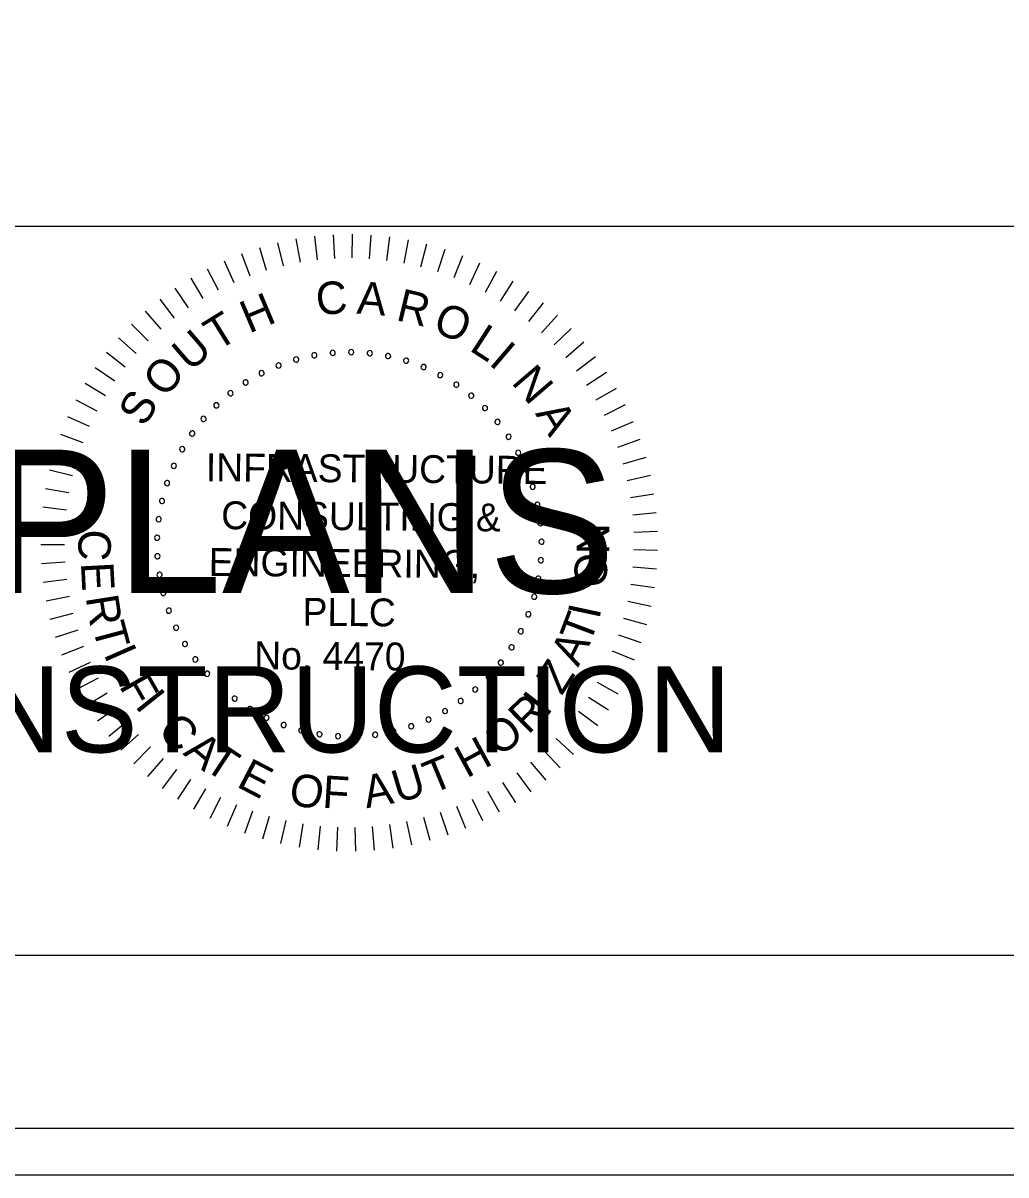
# Model space of a CAD drawing. Extents: x 967 to 1326, y 964 to 3144.
# Drawn here: x 1189.3 to 1212.88, y 963.72 to 991.36 of the extents above; entities that cross this region are included whole.
import ezdxf

# ---------------------------------------------------------------- set-up
doc = ezdxf.new("R2010")
doc.units = 0
for name, color, linetype in [('RD_XS_EwShp', 7, 'Continuous'), ('RD_XS_ExPaveRet', 7, 'Continuous'), ('RD_XS_TX_Elev_EX', 7, 'Continuous'), ('RD_XS_TX_Elev_PR', 7, 'Continuous'), ('RD_XS_TX_Station', 7, 'Continuous')]:
    doc.layers.add(name, color=color, linetype=linetype)

msp = doc.modelspace()

# ---------------------------------------------------------------- linework, layer by layer
at = {"layer": 'RD_XS_ExPaveRet'}
for points in [[(967.409, 963.72), (1326.285, 963.72), (1326.285, 1183.72), (967.409, 1183.72)], [(988.525, 964.84), (1326.285, 964.84), (1326.285, 1182.6), (988.525, 1182.6)]]:
    msp.add_lwpolyline(points, close=True, dxfattribs=at)
at = {"layer": 'RD_XS_TX_Elev_EX'}
for p, q in [((996.114, 986.486), (1323.886, 986.486)), ((1323.886, 968.983), (996.114, 968.983))]:
    msp.add_line(p, q, dxfattribs=at)
at = {"layer": 'RD_XS_TX_Elev_PR'}
for p, q in [((1196.292, 986.245), (1196.357, 985.68)), ((1196.742, 986.282), (1196.772, 985.714)), ((1197.194, 986.292), (1197.189, 985.723)), ((1197.645, 986.274), (1197.606, 985.706)), ((1198.094, 986.228), (1198.02, 985.664)), ((1194.968, 985.971), (1195.134, 985.427)), ((1195.403, 986.09), (1195.536, 985.536)), ((1195.846, 986.181), (1195.945, 985.62)), ((1198.54, 986.156), (1198.432, 985.596)), ((1198.98, 986.056), (1198.838, 985.504)), ((1199.414, 985.929), (1199.238, 985.387)), ((1194.122, 985.656), (1194.353, 985.136)), ((1194.54, 985.827), (1194.739, 985.293)), ((1199.839, 985.777), (1199.63, 985.246)), ((1193.715, 985.461), (1193.978, 984.956)), ((1200.253, 985.598), (1200.013, 985.082)), ((1200.656, 985.395), (1200.385, 984.894)), ((1193.321, 985.241), (1193.614, 984.752)), ((1201.047, 985.167), (1200.745, 984.684)), ((1192.94, 984.997), (1193.263, 984.528)), ((1201.422, 984.917), (1201.092, 984.453)), ((1192.576, 984.731), (1192.926, 984.282)), ((1201.781, 984.643), (1201.424, 984.2)), ((1192.228, 984.443), (1192.605, 984.016)), ((1202.124, 984.349), (1201.739, 983.928)), ((1191.899, 984.134), (1192.301, 983.731)), ((1202.447, 984.034), (1202.038, 983.638)), ((1191.589, 983.805), (1192.015, 983.428)), ((1202.751, 983.7), (1202.318, 983.329)), ((1191.299, 983.459), (1191.748, 983.108)), ((1203.034, 983.348), (1202.579, 983.004)), ((1191.032, 983.095), (1191.501, 982.772)), ((1203.294, 982.979), (1202.82, 982.664)), ((1190.787, 982.716), (1191.274, 982.422)), ((1203.532, 982.595), (1203.04, 982.31)), ((1190.565, 982.323), (1191.07, 982.059)), ((1203.746, 982.198), (1203.237, 981.943)), ((1190.368, 981.916), (1190.888, 981.684)), ((1203.936, 981.788), (1203.412, 981.564)), ((1190.196, 981.499), (1190.729, 981.299)), ((1204.1, 981.367), (1203.563, 981.176)), ((1190.05, 981.072), (1190.594, 980.905)), ((1204.238, 980.937), (1203.691, 980.779)), ((1189.93, 980.636), (1190.484, 980.503)), ((1204.349, 980.5), (1203.794, 980.375)), ((1189.837, 980.195), (1190.398, 980.095)), ((1204.434, 980.056), (1203.872, 979.966)), ((1189.771, 979.748), (1190.337, 979.683)), ((1204.491, 979.608), (1203.925, 979.552)), ((1189.732, 979.298), (1190.301, 979.267)), ((1204.522, 979.158), (1203.953, 979.137)), ((1189.721, 978.847), (1190.29, 978.851)), ((1204.524, 978.706), (1203.955, 978.72)), ((1189.737, 978.396), (1190.306, 978.434)), ((1204.499, 978.256), (1203.932, 978.304)), ((1189.781, 977.946), (1190.346, 978.019)), ((1204.447, 977.807), (1203.884, 977.89)), ((1189.852, 977.5), (1190.412, 977.608)), ((1204.367, 977.363), (1203.81, 977.479)), ((1189.951, 977.06), (1190.502, 977.201)), ((1204.261, 976.924), (1203.712, 977.074)), ((1190.076, 976.626), (1190.617, 976.8)), ((1204.128, 976.492), (1203.589, 976.676)), ((1190.227, 976.2), (1190.757, 976.408)), ((1203.969, 976.07), (1203.442, 976.286)), ((1190.403, 975.785), (1190.92, 976.024)), ((1203.784, 975.658), (1203.271, 975.906)), ((1190.605, 975.381), (1191.106, 975.651)), ((1203.574, 975.258), (1203.078, 975.537)), ((1190.831, 974.99), (1191.315, 975.291)), ((1203.341, 974.871), (1202.862, 975.18)), ((1191.081, 974.614), (1191.545, 974.943)), ((1191.353, 974.253), (1191.796, 974.61)), ((1203.085, 974.5), (1202.626, 974.837)), ((1202.806, 974.145), (1202.368, 974.509)), ((1191.646, 973.91), (1192.067, 974.293)), ((1202.506, 973.807), (1202.092, 974.197)), ((1191.96, 973.585), (1192.356, 973.994)), ((1202.186, 973.488), (1201.796, 973.903)), ((1192.293, 973.28), (1192.664, 973.712)), ((1201.847, 973.19), (1201.484, 973.628)), ((1192.644, 972.996), (1192.988, 973.45)), ((1193.011, 972.734), (1193.327, 973.208)), ((1201.491, 972.912), (1201.155, 973.372)), ((1193.394, 972.495), (1193.68, 972.987)), ((1200.731, 972.425), (1200.453, 972.922)), ((1201.119, 972.657), (1200.811, 973.136)), ((1193.791, 972.279), (1194.047, 972.788)), ((1200.331, 972.217), (1200.083, 972.73)), ((1194.2, 972.088), (1194.424, 972.612)), ((1194.62, 971.923), (1194.812, 972.459)), ((1199.495, 971.877), (1199.312, 972.416)), ((1199.918, 972.034), (1199.702, 972.561)), ((1195.05, 971.783), (1195.208, 972.33)), ((1195.487, 971.67), (1195.612, 972.225)), ((1195.93, 971.584), (1196.021, 972.146)), ((1196.377, 971.524), (1196.434, 972.091)), ((1198.179, 971.562), (1198.097, 972.126)), ((1198.624, 971.64), (1198.508, 972.198)), ((1199.063, 971.745), (1198.913, 972.295)), ((1196.828, 971.493), (1196.85, 972.062)), ((1197.279, 971.488), (1197.267, 972.058)), ((1197.73, 971.512), (1197.683, 972.079))]:
    msp.add_line(p, q, dxfattribs=at)
for centre, start, end in [((1196.285, 983.388), 10.6038, 190.6038), ((1196.727, 983.447), 5.0653, 185.0653), ((1196.727, 983.447), 185.0653, 5.0653), ((1197.172, 983.464), 359.5268, 179.5268), ((1197.172, 983.464), 179.5268, 359.5268), ((1197.617, 983.438), 173.9884, 353.9884), ((1197.617, 983.438), 353.9884, 173.9884), ((1198.057, 983.369), 348.4499, 168.4499), ((1195.429, 983.142), 21.6807, 201.6807), ((1195.429, 983.142), 201.6807, 21.6807), ((1195.851, 983.285), 16.1422, 196.1422), ((1195.851, 983.285), 196.1422, 16.1422), ((1196.285, 983.388), 190.6038, 10.6038), ((1198.057, 983.369), 168.4499, 348.4499), ((1198.489, 983.258), 162.9114, 342.9114), ((1198.489, 983.258), 342.9114, 162.9114), ((1198.908, 983.106), 337.373, 157.373), ((1195.023, 982.958), 27.2191, 207.2191), ((1195.023, 982.958), 207.2191, 27.2191), ((1198.908, 983.106), 157.373, 337.373), ((1199.31, 982.914), 151.8345, 331.8345), ((1199.31, 982.914), 331.8345, 151.8345), ((1194.637, 982.736), 32.7576, 212.7576), ((1194.637, 982.736), 212.7576, 32.7576), ((1199.692, 982.684), 146.2961, 326.2961), ((1199.692, 982.684), 326.2961, 146.2961), ((1194.274, 982.478), 38.2961, 218.2961), ((1194.274, 982.478), 218.2961, 38.2961), ((1200.05, 982.419), 140.7576, 320.7576), ((1200.05, 982.419), 320.7576, 140.7576), ((1193.937, 982.186), 43.8345, 223.8345), ((1193.937, 982.186), 223.8345, 43.8345), ((1200.38, 982.12), 135.2191, 315.2191), ((1200.38, 982.12), 315.2191, 135.2191), ((1193.63, 981.862), 49.373, 229.373), ((1193.63, 981.862), 229.373, 49.373), ((1200.68, 981.79), 129.6807, 309.6807), ((1200.68, 981.79), 309.6807, 129.6807), ((1193.356, 981.511), 54.9114, 234.9114), ((1193.356, 981.511), 234.9114, 54.9114), ((1200.947, 981.433), 304.1422, 124.1422), ((1200.947, 981.433), 124.1422, 304.1422), ((1193.117, 981.135), 60.4499, 240.4499), ((1193.117, 981.135), 240.4499, 60.4499), ((1201.179, 981.052), 118.6038, 298.6038), ((1201.179, 981.052), 298.6038, 118.6038), ((1192.915, 980.737), 65.9884, 245.9884), ((1192.915, 980.737), 245.9884, 65.9884), ((1201.372, 980.651), 113.0653, 293.0653), ((1201.372, 980.651), 293.0653, 113.0653), ((1192.753, 980.322), 71.5268, 251.5268), ((1192.753, 980.322), 251.5268, 71.5268), ((1201.526, 980.233), 107.5268, 287.5268), ((1201.526, 980.233), 287.5268, 107.5268), ((1192.632, 979.894), 77.0653, 257.0653), ((1192.632, 979.894), 257.0653, 77.0653), ((1201.638, 979.801), 101.9884, 281.9884), ((1201.638, 979.801), 281.9884, 101.9884), ((1192.552, 979.455), 82.6038, 262.6038), ((1192.552, 979.455), 262.6038, 82.6038), ((1201.709, 979.361), 96.4499, 276.4499), ((1201.709, 979.361), 276.4499, 96.4499), ((1192.515, 979.011), 88.1422, 268.1422), ((1192.515, 979.011), 268.1422, 88.1422), ((1201.737, 978.917), 90.9114, 270.9114), ((1201.737, 978.917), 270.9114, 90.9114), ((1192.522, 978.565), 93.6807, 273.6807), ((1192.522, 978.565), 273.6807, 93.6807), ((1201.721, 978.471), 85.373, 265.373), ((1201.721, 978.471), 265.373, 85.373), ((1192.571, 978.122), 99.2191, 279.2191), ((1192.571, 978.122), 279.2191, 99.2191), ((1201.663, 978.029), 79.8345, 259.8345), ((1201.663, 978.029), 259.8345, 79.8345), ((1192.662, 977.686), 104.7576, 284.7576), ((1192.662, 977.686), 284.7576, 104.7576), ((1201.563, 977.595), 74.2961, 254.2961), ((1201.563, 977.595), 254.2961, 74.2961), ((1192.796, 977.261), 110.2961, 290.2961), ((1192.796, 977.261), 290.2961, 110.2961), ((1201.42, 977.173), 68.7576, 248.7576), ((1201.42, 977.173), 248.7576, 68.7576), ((1192.97, 976.851), 115.8345, 295.8345), ((1192.97, 976.851), 295.8345, 115.8345), ((1201.238, 976.766), 63.2191, 243.2191), ((1201.238, 976.766), 243.2191, 63.2191), ((1193.182, 976.459), 301.373, 121.373), ((1193.182, 976.459), 121.373, 301.373), ((1201.018, 976.379), 57.6807, 237.6807), ((1201.018, 976.379), 237.6807, 57.6807), ((1193.432, 976.09), 126.9114, 306.9114), ((1193.432, 976.09), 306.9114, 126.9114), ((1200.761, 976.014), 52.1422, 232.1422), ((1200.761, 976.014), 232.1422, 52.1422), ((1193.715, 975.746), 132.4499, 312.4499), ((1193.715, 975.746), 312.4499, 132.4499), ((1200.47, 975.677), 46.6038, 226.6038), ((1200.47, 975.677), 226.6038, 46.6038), ((1194.031, 975.431), 137.9884, 317.9884), ((1194.031, 975.431), 317.9884, 137.9884), ((1200.148, 975.369), 41.0653, 221.0653), ((1200.148, 975.369), 221.0653, 41.0653), ((1194.376, 975.149), 143.5268, 323.5268), ((1194.376, 975.149), 323.5268, 143.5268), ((1199.798, 975.093), 35.5268, 215.5268), ((1194.746, 974.901), 149.0653, 329.0653), ((1194.746, 974.901), 329.0653, 149.0653), ((1199.422, 974.853), 29.9884, 209.9884), ((1199.422, 974.853), 209.9884, 29.9884), ((1199.798, 975.093), 215.5268, 35.5268), ((1195.139, 974.69), 154.6038, 334.6038), ((1195.139, 974.69), 334.6038, 154.6038), ((1195.55, 974.517), 340.1422, 160.1422), ((1199.026, 974.65), 24.4499, 204.4499), ((1199.026, 974.65), 204.4499, 24.4499), ((1195.55, 974.517), 160.1422, 340.1422), ((1195.975, 974.386), 165.6807, 345.6807), ((1195.975, 974.386), 345.6807, 165.6807), ((1196.412, 974.295), 171.2191, 351.2191), ((1196.412, 974.295), 351.2191, 171.2191), ((1196.855, 974.248), 356.7576, 176.7576), ((1197.301, 974.243), 2.2961, 182.2961), ((1197.745, 974.282), 7.8345, 187.8345), ((1198.183, 974.363), 13.373, 193.373), ((1198.183, 974.363), 193.373, 13.373), ((1198.611, 974.486), 18.9114, 198.9114), ((1198.611, 974.486), 198.9114, 18.9114), ((1196.855, 974.248), 176.7576, 356.7576), ((1197.301, 974.243), 182.2961, 2.2961), ((1197.745, 974.282), 187.8345, 7.8345)]:
    msp.add_arc(centre, 0.0627, start, end, dxfattribs=at)
at = {"layer": 'RD_XS_TX_Station'}
msp.add_lwpolyline([(967.409, 963.72), (1326.285, 963.72), (1326.285, 1183.72), (967.409, 1183.72)], close=True, dxfattribs=at)

# ---------------------------------------------------------------- texts
at = {"layer": 'RD_XS_EwShp'}
for s, height, p in [('FINAL PLANS', 3.4375, (1174.145, 977.685)), ('NOT FOR CONSTRUCTION', 2.0625, (1170.901, 973.86))]:
    msp.add_text(s, height=height, dxfattribs=at).set_placement(p)
at = {"layer": 'RD_XS_TX_Elev_PR'}
for s, height, rotation, p in [('C', 0.78, 4.7281, (1196.355, 984.346)), ('A', 0.78, 355.6981, (1197.29, 984.39)), ('H', 0.78, 22.7882, (1194.72, 983.904)), ('R', 0.78, 346.6681, (1198.222, 984.238)), ('O', 0.78, 337.638, (1199.096, 983.972)), ('T', 0.78, 31.8182, (1193.961, 983.478)), ('U', 0.78, 40.8482, (1193.306, 982.976)), ('L', 0.78, 327.108, (1199.981, 983.52)), ('I', 0.78, 319.578, (1200.451, 983.182)), ('O', 0.78, 49.8782, (1192.707, 982.341)), ('N', 0.78, 310.548, (1200.994, 982.728)), ('S', 0.78, 58.9083, (1192.211, 981.642)), ('A', 0.78, 301.5179, (1201.576, 981.991)), ('INFRASTRUCTURE', 0.66873, 359.5268, (1193.682, 980.367)), ('CONSULTING &', 0.66873, 359.5268, (1194.051, 979.217)), ('N', 0.78, 89.2085, (1203.359, 978.604)), ('C', 0.78, 267.025, (1190.646, 979.227)), ('ENGINEERING,', 0.66873, 359.5268, (1193.751, 978.095)), ('O', 0.78, 83.2085, (1203.26, 977.786)), ('E', 0.78, 273.025, (1190.685, 978.408)), ('R', 0.78, 279.025, (1190.799, 977.583)), ('PLLC', 0.6687, 359.5268, (1196.002, 976.9)), ('I', 0.78, 77.9093, (1203.121, 977.032)), ('T', 0.78, 69.3954, (1202.891, 976.428)), ('T', 0.78, 285.025, (1190.955, 976.878)), ('No. 4470', 0.6687, 359.5268, (1194.843, 975.855)), ('A', 0.78, 63.3954, (1202.616, 975.888)), ('I', 0.78, 293.7713, (1191.221, 976.225)), ('Z', 0.78, 57.3954, (1202.224, 975.206)), ('F', 0.78, 299.7713, (1191.589, 975.455)), ('I', 0.78, 308.5268, (1191.965, 974.973)), ('R', 0.78, 44.5268, (1201.415, 974.267)), ('I', 0.78, 52.3339, (1201.856, 974.69)), ('C', 0.78, 314.5268, (1192.496, 974.346)), ('O', 0.78, 38.5268, (1200.73, 973.731)), ('A', 0.78, 320.5268, (1193.115, 973.822)), ('T', 0.78, 326.5268, (1193.602, 973.478)), ('H', 0.78, 28.5268, (1199.942, 973.23)), ('T', 0.78, 22.5268, (1199.108, 972.856)), ('E', 0.78, 332.5268, (1194.394, 973.051)), ('U', 0.78, 16.5268, (1198.288, 972.638)), ('O', 0.78, 350.5268, (1195.647, 972.614)), ('F', 0.78, 356.5268, (1196.465, 972.532)), ('A', 0.78, 10.5268, (1197.537, 972.517))]:
    msp.add_text(s, height=height, rotation=rotation, dxfattribs=at).set_placement(p)

doc.saveas('drawing.dxf')
